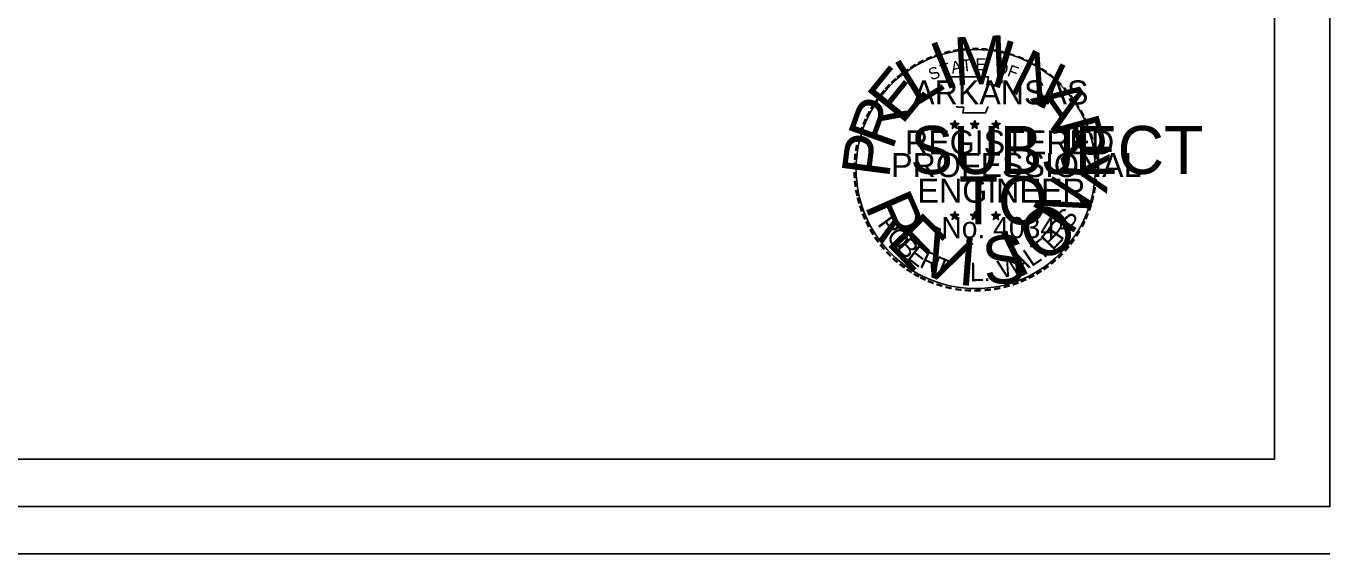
# Model space of a CAD drawing. Extents: x 21307 to 29830, y 1322443 to 1332359.
# Drawn here: x 26008 to 27092, y 1325370 to 1325809 of the extents above; entities that cross this region are included whole.
import ezdxf

# ---------------------------------------------------------------- set-up
doc = ezdxf.new("R2010")
doc.units = 0
for name, color, linetype in [('62', 7, 'Continuous'), ('R_Draft', 7, 'Continuous'), ('R_No Plot', 7, 'Continuous')]:
    doc.layers.add(name, color=color, linetype=linetype)

msp = doc.modelspace()

# ---------------------------------------------------------------- linework, layer by layer
at = {"layer": '62'}
for p, q in [((26779.8, 1325730.2), (26779.4, 1325727.7)), ((26779.8, 1325726.6), (26779.8, 1325730.2)), ((26779.8, 1325730.2), (26780.3, 1325727.7)), ((26796.5, 1325730.2), (26796.1, 1325727.7)), ((26796.5, 1325726.6), (26796.5, 1325730.2)), ((26796.5, 1325730.2), (26797, 1325727.7)), ((26814.2, 1325730.1), (26813.7, 1325727.6)), ((26814.2, 1325726.5), (26814.2, 1325730.1)), ((26814.2, 1325730.1), (26814.6, 1325727.6)), ((26776.3, 1325727.7), (26779.8, 1325726.6)), ((26776.3, 1325727.7), (26778.9, 1325727.2)), ((26776.3, 1325727.7), (26778.7, 1325726.5)), ((26777.7, 1325723.6), (26779.8, 1325726.6)), ((26777.7, 1325723.6), (26778.9, 1325726.1)), ((26777.7, 1325723.6), (26779.8, 1325725.8)), ((26783.3, 1325727.7), (26779.8, 1325726.6)), ((26781.9, 1325723.6), (26779.8, 1325726.6)), ((26781.9, 1325723.6), (26779.8, 1325725.8)), ((26783.3, 1325727.7), (26780.4, 1325727.2)), ((26781.9, 1325723.6), (26780.6, 1325726.5)), ((26783.3, 1325727.7), (26781.2, 1325726.7)), ((26793, 1325727.7), (26796.5, 1325726.6)), ((26793, 1325727.7), (26795.6, 1325727.2)), ((26793, 1325727.7), (26795.4, 1325726.5)), ((26794.4, 1325723.6), (26796.5, 1325726.6)), ((26794.4, 1325723.6), (26795.6, 1325726.1)), ((26794.4, 1325723.6), (26796.5, 1325725.8)), ((26800, 1325727.7), (26796.5, 1325726.6)), ((26798.6, 1325723.6), (26796.5, 1325726.6)), ((26798.6, 1325723.6), (26796.5, 1325725.8)), ((26800, 1325727.7), (26797.1, 1325727.2)), ((26798.6, 1325723.6), (26797.3, 1325726.5)), ((26800, 1325727.7), (26797.9, 1325726.7)), ((26810.7, 1325727.6), (26814.2, 1325726.5)), ((26810.7, 1325727.6), (26813.2, 1325727.1)), ((26810.7, 1325727.6), (26813, 1325726.4)), ((26812, 1325723.5), (26814.2, 1325726.5)), ((26812, 1325723.5), (26813.3, 1325725.9)), ((26812, 1325723.5), (26814.1, 1325725.7)), ((26816.3, 1325723.5), (26814.1, 1325725.6)), ((26817.6, 1325727.6), (26814.2, 1325726.5)), ((26816.3, 1325723.5), (26814.2, 1325726.5)), ((26817.6, 1325727.6), (26814.8, 1325727.1)), ((26816.3, 1325723.5), (26814.9, 1325726.4)), ((26817.6, 1325727.6), (26815.6, 1325726.6)), ((26779.8, 1325654.5), (26779.4, 1325652)), ((26779.8, 1325650.9), (26779.8, 1325654.5)), ((26779.8, 1325654.5), (26780.3, 1325652)), ((26796.5, 1325654.5), (26796.1, 1325652)), ((26796.5, 1325650.9), (26796.5, 1325654.5)), ((26796.5, 1325654.5), (26797, 1325652)), ((26814.1, 1325654.4), (26813.7, 1325651.9)), ((26814.1, 1325650.8), (26814.1, 1325654.4)), ((26814.1, 1325654.4), (26814.6, 1325651.9)), ((26776.3, 1325652), (26779.8, 1325650.9)), ((26776.3, 1325652), (26778.8, 1325651.5)), ((26776.3, 1325652), (26778.7, 1325650.7)), ((26777.6, 1325647.9), (26779.8, 1325650.9)), ((26777.6, 1325647.9), (26778.9, 1325650.3)), ((26777.6, 1325647.9), (26779.8, 1325650.1)), ((26783.2, 1325652), (26779.8, 1325650.9)), ((26781.9, 1325647.9), (26779.8, 1325650.9)), ((26781.9, 1325647.9), (26779.8, 1325650)), ((26783.2, 1325652), (26780.4, 1325651.5)), ((26781.9, 1325647.9), (26780.5, 1325650.8)), ((26783.2, 1325652), (26781.2, 1325650.9)), ((26793, 1325652), (26796.5, 1325650.9)), ((26793, 1325652), (26795.5, 1325651.5)), ((26793, 1325652), (26795.3, 1325650.7)), ((26794.3, 1325647.9), (26796.5, 1325650.9)), ((26794.3, 1325647.9), (26795.6, 1325650.3)), ((26794.3, 1325647.9), (26796.4, 1325650.1)), ((26798.6, 1325647.9), (26796.4, 1325650)), ((26799.9, 1325652), (26796.5, 1325650.9)), ((26798.6, 1325647.9), (26796.5, 1325650.9)), ((26799.9, 1325652), (26797.1, 1325651.5)), ((26798.6, 1325647.9), (26797.2, 1325650.8)), ((26799.9, 1325652), (26797.9, 1325650.9)), ((26810.6, 1325651.9), (26814.1, 1325650.8)), ((26810.6, 1325651.9), (26813.2, 1325651.4)), ((26810.6, 1325651.9), (26813, 1325650.6)), ((26812, 1325647.8), (26814.1, 1325650.8)), ((26812, 1325647.8), (26813.2, 1325650.2)), ((26812, 1325647.8), (26814.1, 1325650)), ((26817.6, 1325651.9), (26814.1, 1325650.8)), ((26816.3, 1325647.8), (26814.1, 1325650.8)), ((26816.3, 1325647.8), (26814.1, 1325649.9)), ((26817.6, 1325651.9), (26814.7, 1325651.4)), ((26816.3, 1325647.8), (26814.9, 1325650.7)), ((26817.6, 1325651.9), (26815.6, 1325650.8))]:
    msp.add_line(p, q, dxfattribs=at)
for points in [[(26776.7, 1325766.5), (26779.4, 1325758.2)], [(26811.8, 1325757.3), (26813.3, 1325760.1), (26806.4, 1325759.9), (26807.9, 1325766.5), (26776.7, 1325766.5)], [(26781.7, 1325742.2), (26781.7, 1325741.4), (26787.3, 1325741.2), (26786.7, 1325736.5), (26805.4, 1325736.5), (26807.5, 1325741.8)], [(26779.8, 1325730.2), (26781.9, 1325723.6), (26776.3, 1325727.7), (26783.3, 1325727.7), (26777.7, 1325723.6), (26779.8, 1325730.2)], [(26796.5, 1325730.2), (26798.6, 1325723.6), (26793, 1325727.7), (26800, 1325727.7), (26794.4, 1325723.6), (26796.5, 1325730.2)], [(26814.2, 1325730.1), (26816.3, 1325723.5), (26810.7, 1325727.6), (26817.6, 1325727.6), (26812, 1325723.5), (26814.2, 1325730.1)], [(26779.8, 1325654.5), (26781.9, 1325647.9), (26776.3, 1325652), (26783.2, 1325652), (26777.6, 1325647.9), (26779.8, 1325654.5)], [(26796.5, 1325654.5), (26798.6, 1325647.9), (26793, 1325652), (26799.9, 1325652), (26794.3, 1325647.9), (26796.5, 1325654.5)], [(26814.1, 1325654.4), (26816.3, 1325647.8), (26810.6, 1325651.9), (26817.6, 1325651.9), (26812, 1325647.8), (26814.1, 1325654.4)]]:
    msp.add_lwpolyline(points, dxfattribs=at)
for centre, radius in [((26779.8, 1325726.6), 1.72), ((26779.8, 1325726.6), 1.45), ((26779.8, 1325726.6), 1.16), ((26779.8, 1325726.6), 0.991), ((26779.8, 1325726.6), 0.747), ((26779.8, 1325726.6), 0.495), ((26779.8, 1325726.6), 0.296), ((26796.5, 1325726.6), 1.72), ((26796.5, 1325726.6), 1.45), ((26796.5, 1325726.6), 1.16), ((26796.5, 1325726.6), 0.991), ((26796.5, 1325726.6), 0.747), ((26796.5, 1325726.6), 0.495), ((26796.5, 1325726.6), 0.296), ((26814.1, 1325726.5), 1.72), ((26814.1, 1325726.5), 1.45), ((26814.1, 1325726.5), 1.16), ((26814.1, 1325726.5), 0.991), ((26814.1, 1325726.5), 0.747), ((26814.1, 1325726.5), 0.495), ((26814.1, 1325726.5), 0.296), ((26779.8, 1325650.9), 1.72), ((26779.8, 1325650.9), 1.45), ((26779.8, 1325650.9), 1.16), ((26779.8, 1325650.9), 0.991), ((26779.8, 1325650.9), 0.747), ((26779.8, 1325650.9), 0.495), ((26779.8, 1325650.9), 0.296), ((26796.5, 1325650.9), 1.72), ((26796.5, 1325650.9), 1.45), ((26796.5, 1325650.9), 1.16), ((26796.5, 1325650.9), 0.991), ((26796.5, 1325650.9), 0.747), ((26796.5, 1325650.9), 0.495), ((26796.5, 1325650.9), 0.296), ((26814.1, 1325650.8), 1.72), ((26814.1, 1325650.8), 1.45), ((26814.1, 1325650.8), 1.16), ((26814.1, 1325650.8), 0.991), ((26814.1, 1325650.8), 0.747), ((26814.1, 1325650.8), 0.495), ((26814.1, 1325650.8), 0.296)]:
    msp.add_circle(centre, radius, dxfattribs=at)
at = {"layer": 'R_Draft'}
for p, q in [((27045.7, 1325448.4), (27045.7, 1327502.8)), ((27045.7, 1325448.4), (23883.9, 1325448.4)), ((23818.2, 1325409), (27091.7, 1325409)), ((23818.2, 1325369.6), (27091.7, 1325369.6))]:
    msp.add_line(p, q, dxfattribs=at)
msp.add_circle((26797.2, 1325689.8), 99.4, dxfattribs=at)
at = {"layer": 'R_No Plot'}
msp.add_lwpolyline([(23808.3, 1327542.3), (27091.7, 1327542.3), (27091.7, 1325409), (23808.3, 1325409)], close=True, dxfattribs=at)

# ---------------------------------------------------------------- texts
at = {"layer": '62'}
for s, height, rotation, p in [('-', 16, 24.3072, (26757.9, 1325775.1)), ('-', 16, 19.1761, (26764.2, 1325777.7)), ('-', 16, 13.6302, (26771.7, 1325780.2)), ('-', 16, 10.2193, (26778.5, 1325781.8)), ('-', 16, 5.8968, (26785.8, 1325782.9)), ('-', 16, 0.1862, (26793.5, 1325783.6)), ('-', 16, 357.743, (26800.7, 1325783.5)), ('-', 16, 352.1617, (26808.2, 1325782.9)), ('-', 16, 347.2049, (26815.4, 1325781.8)), ('-', 16, 342.3362, (26821.7, 1325780.2)), ('-', 16, 337.8551, (26829.1, 1325778)), ('-', 16, 36.2317, (26739.8, 1325764.2)), ('-', 16, 34.0636, (26745.6, 1325768.2)), ('-', 16, 28.7918, (26751.5, 1325771.9)), ('S', 10, 21.594, (26760.3, 1325763.3)), ('T', 10, 16.4036, (26769.4, 1325766.6)), ('A', 10, 11.2132, (26777.7, 1325769.1)), ('T', 10, 6.0228, (26786.2, 1325770.7)), ('E', 10, 0.8323, (26797.2, 1325771.8)), ('O', 10, 350.4515, (26813.3, 1325769.7)), ('F', 10, 340.0707, (26822.8, 1325767.5)), ('-', 16, 334.1211, (26835.4, 1325775.3)), ('-', 16, 329.6409, (26841.2, 1325772.4)), ('-', 16, 325.8627, (26847.6, 1325768.8)), ('-', 16, 42.9622, (26730.7, 1325756.3)), ('-', 16, 38.9507, (26735, 1325760.5)), ('-', 16, 320.5297, (26853.7, 1325764.6)), ('-', 16, 315.5786, (26859.7, 1325759.7)), ('-', 16, 50.6142, (26722.2, 1325746.6)), ('-', 16, 48.4231, (26726.2, 1325751.5)), ('-', 16, 309.8797, (26865.4, 1325754.2)), ('-', 16, 306.6522, (26870.6, 1325748.2)), ('-', 16, 58.0706, (26714.8, 1325735.7)), ('-', 16, 54.2325, (26718.1, 1325741)), ('-', 14, 303.6753, (26875.5, 1325742.5)), ('-', 16, 67.7743, (26709.1, 1325723.5)), ('-', 16, 62.8713, (26711.7, 1325729.6)), ('-', 16, 299.6684, (26878.7, 1325736.4)), ('-', 16, 294.6628, (26881.9, 1325730.3)), ('-', 16, 72.3945, (26706.9, 1325717.2)), ('-', 16, 290.5728, (26884.5, 1325724.5)), ('-', 16, 285.1233, (26886.8, 1325718.7)), ('-', 16, 81.2013, (26703.6, 1325702.9)), ('-', 16, 75.461, (26704.9, 1325710)), ('-', 16, 280.5493, (26888.8, 1325711.3)), ('-', 16, 85.1863, (26702.8, 1325696)), ('-', 16, 276.5962, (26890.4, 1325703.6)), ('-', 16, 94.1959, (26702.9, 1325681.7)), ('-', 16, 89.0622, (26702.6, 1325689)), ('-', 16, 274.3301, (26891, 1325696.4)), ('-', 16, 269.9407, (26891.4, 1325690.1)), ('-', 16, 98.9479, (26703.7, 1325675)), ('-', 16, 260.9953, (26890.5, 1325676.9)), ('-', 16, 263.5172, (26891.2, 1325683.4)), ('-', 16, 101.7149, (26705, 1325667.7)), ('-', 16, 105.4578, (26706.6, 1325661.8)), ('-', 16, 255.7626, (26889.4, 1325670.1)), ('-', 16, 109.0874, (26708.8, 1325655.5)), ('-', 16, 114.0643, (26711.3, 1325649.5)), ('S', 15.4, 55.055, (26875.3, 1325639.1)), ('-', 16, 247.8887, (26885.3, 1325656.2)), ('-', 16, 252.8681, (26887.6, 1325662.9)), ('-', 16, 115.7289, (26714.4, 1325643.3)), ('R', 15.4, 306.6553, (26715.1, 1325643.9)), ('R', 15.4, 55.4855, (26868.6, 1325629.5)), ('-', 16, 244.6197, (26882.7, 1325649.9)), ('-', 16, 120.4471, (26717.9, 1325637.5)), ('-', 16, 125.8934, (26722, 1325631.8)), ('O', 15.4, 311.2689, (26722.2, 1325633.1)), ('B', 15.4, 312.5498, (26730.6, 1325624.1)), ('T', 15.4, 36.1097, (26850.8, 1325613)), ('E', 15.4, 46.226, (26861.1, 1325621.4)), ('-', 16, 233.8452, (26874.8, 1325635.8)), ('-', 16, 239.0712, (26878.8, 1325642.4)), ('-', 16, 130.7181, (26726.6, 1325626.3)), ('-', 16, 134.2238, (26731.8, 1325620.9)), ('E', 15.4, 322.5001, (26739.4, 1325615.7)), ('R', 15.4, 334.6461, (26749.7, 1325608.8)), ('L', 15.4, 33.4326, (26843.5, 1325608)), ('-', 16, 231.2538, (26870.5, 1325630.2)), ('-', 16, 138.9338, (26737, 1325616.2)), ('-', 16, 144.6463, (26742.6, 1325612.2)), ('T', 15.4, 337.4846, (26760.5, 1325603.4)), ('L.', 15.4, 0.5107, (26792.5, 1325596.5)), ('W', 15.4, 17.8991, (26818.8, 1325598.4)), ('A', 15.4, 24.2455, (26830.7, 1325602.5)), ('-', 16, 215.7363, (26855, 1325614.7)), ('-', 16, 221.0851, (26860.4, 1325619.5)), ('-', 16, 225.7653, (26865.7, 1325624.5)), ('-', 16, 148.0898, (26748.2, 1325608.5)), ('-', 16, 151.5704, (26754, 1325605.2)), ('-', 16, 154.6002, (26759.2, 1325602.7)), ('-', 16, 204.2516, (26837.8, 1325604.2)), ('-', 16, 207.3568, (26844, 1325607.4)), ('-', 16, 212.2491, (26849.6, 1325610.9)), ('-', 16, 158.5612, (26765.4, 1325600.2)), ('-', 16, 162.7983, (26772.3, 1325598.1)), ('-', 16, 167.5555, (26779.5, 1325596.4)), ('-', 16, 173.1155, (26787.2, 1325595.3)), ('-', 16, 176.5183, (26794.7, 1325594.8)), ('-', 16, 181.5918, (26802.1, 1325595)), ('-', 16, 185.8167, (26810.2, 1325595.8)), ('-', 16, 191.2858, (26817.5, 1325597.1)), ('-', 16, 195.4743, (26824.8, 1325599.1)), ('-', 16, 200.7184, (26831.6, 1325601.5))]:
    msp.add_text(s, height=height, rotation=rotation, dxfattribs=at).set_placement(p)
for s, height, p in [('ARKANSAS', 20, (26745.3, 1325743.6)), ('REGISTERED', 20, (26738.5, 1325702.1)), ('PROFESSIONAL', 20, (26727, 1325683.1)), ('ENGINEER', 20, (26748.9, 1325661.8)), ('No. 4034', 17.57, (26768.7, 1325632.3))]:
    msp.add_text(s, height=height, dxfattribs=at).set_placement(p)
at = {"layer": 'R_Draft'}
for s, rotation, p in [('I', 22.0105, (26770.9, 1325754.9)), ('M', 2.6943, (26779.6, 1325759.3)), ('I', 343.3781, (26807.8, 1325760)), ('N', 333.7199, (26823.5, 1325755.1)), ('E', 50.9849, (26735.9, 1325725.7)), ('L', 31.6686, (26747.7, 1325741.8)), ('A', 304.7456, (26842.3, 1325748.1)), ('R', 70.3011, (26727.9, 1325704.6)), ('R', 285.4294, (26859.6, 1325727.8)), ('P', 82.6089, (26725.2, 1325681.3)), ('Y', 266.1131, (26868.8, 1325706.3)), ('N', 57.1378, (26876.3, 1325633.4)), ('R', 293.7639, (26704.5, 1325659.5)), ('E', 314.3262, (26721.7, 1325628.2)), ('O', 36.5754, (26852, 1325609.6)), ('V', 334.8885, (26746.5, 1325606.4)), ('I', 355.4508, (26781.7, 1325593.6)), ('S', 5.732, (26804.9, 1325593)), ('I', 26.2943, (26831.6, 1325598.5))]:
    msp.add_text(s, height=40, rotation=rotation, dxfattribs=at).set_placement(p)
for s, p in [('SUBJECT', (26742.8, 1325685.7)), ('TO', (26783.2, 1325643.7))]:
    msp.add_text(s, height=40, dxfattribs=at).set_placement(p)

doc.saveas('drawing.dxf')
